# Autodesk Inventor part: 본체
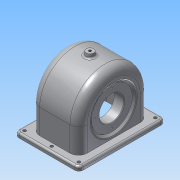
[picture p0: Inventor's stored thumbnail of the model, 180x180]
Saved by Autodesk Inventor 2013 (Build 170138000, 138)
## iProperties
Created: 2015-09
Part Number: 본체
Material: 알루미늄 6061
Document SubType Name: Modeling
Designer: Administrator
Density: 1 g/cm^3
Author: Administrator
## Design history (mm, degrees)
sketch "스케치1"
  geometry: L1 (-57, 0)-(57, 0); L2 (0, 0)-(0, 47); L3 (-57, 0)-(-57, 47); L4 (57, 0)-(57, 47); A1 r 57 centre (0, 47) between (57, 47) and (-57, 47); 1 further point
  constraints: 8 end point, 2 coincident, 2 point on circle, 1 centre point, 1 horizontal, 1 midpoint, 1 parallel, 1 perpendicular
  dimensions: "d0" = 114 distance of L1.start L1.end; "d1" = 47 distance of L2.start L2.end; "d2" = 57 radius of A1
extrude "돌출1" new body sketch "스케치1" stored distance "d3" = 77; taper "d4" = 0 deg
feature "쉘1" dims "d5" = 5
sketch "스케치2"
  geometry: L1 (47, -57)-(0, -57) reference; L2 (0, -57)-(0, 57) reference; L3 (0, 57)-(47, 57) reference; C1 r 31 at (47, 0); A1 r 57 centre (47, 0) between (47, -57) and (47, 57) reference; 1 further point
  constraints: 1 centre point, 1 coincident
  dimensions: "d6" = 62 diameter of C1
extrude "돌출2" join sketch "스케치2" distance "d7" = 10; taper "d8" = 0 deg
sketch "스케치3"
  geometry: C1 r 31 at (0, 0) reference; C2 r 20 at (0, 0); 1 further point
  constraints: 1 centre point, 1 coincident
  dimensions: "d9" = 40 diameter of C2
extrude "돌출3" cut sketch "스케치3" stored distance "d10" = 10; taper "d11" = 0 deg
fillet "모깎기1" dims "d12" = 14
fillet "모깎기2" dims "d13" = 3
chamfer "모따기1" distance "d14" = 1; stored, may be unused: second distance "d15" = 2, angle "d16" = 45 deg
fillet "모깎기3" dims "d17" = 9
sketch "스케치4"
  geometry: C1 r 21 at (0, 0) reference; C2 r 31 at (0, 0) reference; A1 r 24 centre (0, 0) between (0, 24) and (-24, 0); 3 further points
  constraints: 4 point on circle, 1 centre point, 1 coincident
  dimensions: "d18" = 48 diameter of A1
hole "구멍1" sketch "스케치4" at (0, 24), (-24, 0), (0, -24), (24, 0) diameter "d19" = 2.459; stored, may be unused: countersink angle "d23" = 90 deg, drill point angle "d25" = 118 deg; dims "d20" = 6, "d21" = 4, "d22" = 2, "d24" = 8
sketch "스케치5"
  geometry: L1 (0, 43)-(-47, 43) reference; L2 (-47, -43)-(0, -43) reference; L3 (0, 43)-(0, -43) reference; C1 r 28 at (-47, 0); A1 r 43 centre (-47, 0) between (-47, 43) and (-47, -43) reference; 1 further point
  constraints: 1 centre point, 1 coincident
  dimensions: "d26" = 56 diameter of C1
extrude "돌출4" join sketch "스케치5" distance "d27" = 19; taper "d28" = 0 deg
sketch "스케치6"
  geometry: L1 (0, 43)-(-47, 43) reference; L2 (-47, -43)-(0, -43) reference; L3 (0, 43)-(0, -43) reference; C1 r 33 at (-47, 0); A1 r 43 centre (-47, 0) between (-47, 43) and (-47, -43) reference; 1 further point
  constraints: 1 centre point, 1 coincident
  dimensions: "d29" = 66 diameter of C1
extrude "돌출5" cut sketch "스케치6" distance "d30" = 3; taper "d31" = 0 deg
sketch "스케치7"
  geometry: L1 (0, 51.66)-(47, 51.66) reference; L2 (47, 51.66)-(47, -51.66) reference; L3 (47, -51.66)-(0, -51.66) reference; C1 r 33 at (0, 0) reference; C2 r 20 at (0, 0); A1 r 51.66 centre (0, 0) between (0, 51.66) and (0, -51.66) reference; 1 further point
  constraints: 1 centre point, 1 coincident
  dimensions: "d32" = 40 diameter of C2
extrude "돌출6" cut sketch "스케치7" stored distance "d33" = 3; taper "d34" = 0 deg
feature "면 기울기1" dims angle "d35" = 40 deg
node "작업 평면1"
sketch "스케치8"
  geometry: L1 (44, -19)-(58, -7.253) reference; L2 (58, -7.253)-(58, 0) reference; L3 (58, 0)-(63, 0) reference; L4 (63, 0)-(63, -14) reference; L5 (63, -14)-(60, -14) reference; L6 (60, -14)-(60, -27) reference; L7 (60, -27)-(44, -27) reference; L8 (44, -27)-(44, -19) reference; L9 (-14, -13)-(-14, 0) reference; L10 (-14, 0)-(-9, 0) reference; L11 (-9, 0)-(-9, -27) reference; L12 (-9, -27)-(-23, -27) reference; L13 (-23, -27)-(-24, -26) reference; L14 (-24, -26)-(-24, -24.229) reference; L15 (-24, -24.229)-(-16, -24.229) reference; L16 (-16, -24.229)-(-15.261, -23) reference; L17 (-15.261, -23)-(-16, -21.77) reference; L18 (-16, -21.77)-(-24, -21.77) reference; L19 (-24, -21.77)-(-24, -16) reference; L20 (-24, -16)-(-17, -16) reference; L21 (49, -104)-(0, -104) reference; L22 (-14, -90)-(-14, -81) reference; L23 (-17, -78)-(-24, -78) reference; L24 (-24, -78)-(-24, -72.23) reference; L25 (-24, -72.23)-(-16, -72.23) reference; L26 (-16, -72.23)-(-15.261, -71) reference; L27 (-15.261, -71)-(-16, -69.77) reference; L28 (-16, -69.77)-(-24, -69.77) reference; L29 (-24, -69.77)-(-24, -68) reference; L30 (-24, -68)-(-23, -67) reference; L31 (-23, -67)-(-9, -67) reference; L32 (-9, -67)-(-9, -90) reference; L33 (0, -99)-(49, -99) reference; L34 (58, -90)-(58, -86.747) reference; L35 (58, -86.747)-(44, -75) reference; L36 (44, -75)-(44, -67) reference; L37 (44, -67)-(60, -67) reference; L38 (60, -67)-(60, -80) reference; L39 (60, -80)-(63, -80) reference; L40 (63, -80)-(63, -90) reference; L41 (58, -86.747)-(44, -75); L42 (63, -84.416)-(58.79, -80.883); L43 (63, -84.416)-(63, -80); L44 (63, -80)-(59.111, -80); L45 (60, -67)-(60, -27); L46 (60, -47)-(88.26, -47); A1 r 3 centre (-17, -13) between (-17, -16) and (-14, -13) reference; A2 r 14 centre (49, -90) between (49, -104) and (63, -90) reference; A3 r 14 centre (0, -90) between (-14, -90) and (0, -104) reference; A4 r 3 centre (-17, -81) between (-14, -81) and (-17, -78) reference; A5 r 9 centre (0, -90) between (-9, -90) and (0, -99) reference; A6 r 9 centre (49, -90) between (49, -99) and (58, -90) reference; A7 r 0.5 centre (59.111, -80.5) between (59.111, -80) and (58.79, -80.883); 1 further point
  constraints: 12 end point, 3 perpendicular, 2 collinear, 2 point on circle, 2 tangent, 1 centre point, 1 midpoint, 1 parallel, 1 point on line
  dimensions: "d36" = 5 distance between parallel lines of L35 L42; "d37" = 0.5 radius of A7
revolve "회전1" sketch "스케치8" stored, may be unused: angle "d38" = 90 deg
chamfer "모따기2" distance "d39" = 1; stored, may be unused: second distance "d40" = 2, angle "d41" = 45 deg
sketch "스케치9"
  geometry: L1 (0, 51.66)-(47, 51.66) reference; L2 (47, 51.66)-(47, -51.66) reference; L3 (47, -51.66)-(0, -51.66) reference; C1 r 21 at (0, 0) reference; C2 r 34.899 at (0, 0) reference; C3 r 33 at (0, 0) reference; A1 r 51.66 centre (0, 0) between (0, 51.66) and (0, -51.66) reference; A2 r 28 centre (0, 0) between (-28, 0) and (0, -28); 3 further points
  constraints: 4 point on circle, 1 centre point, 1 coincident
  dimensions: "d42" = 56 diameter of A2
hole "구멍2" sketch "스케치9" at (-28, 0), (0, -28), (28, 0), (0, 28) diameter "d43" = 2.459; stored, may be unused: countersink angle "d47" = 82 deg, drill point angle "d49" = 118 deg; dims "d44" = 7, "d45" = 3.023, "d46" = 2, "d48" = 9
sketch "스케치10"
  geometry: L1 (-33.5, 43)-(-33.5, -43) reference; L2 (-24.5, -52)-(24.5, -52) reference; L3 (33.5, -43)-(33.5, 43) reference; L4 (24.5, 52)-(-24.5, 52) reference; L5 (-38.5, -43)-(-38.5, 43) reference; L6 (-24.5, 57)-(24.5, 57) reference; L7 (38.5, 43)-(38.5, -43) reference; L8 (24.5, -57)-(-24.5, -57) reference; L9 (-45, 70)-(45, 70); L10 (52, 63)-(52, -63); L11 (45, -70)-(-45, -70); L12 (-52, -63)-(-52, 63); L13 (0, 70)-(0, 62); L14 (-38.5, 0)-(38.5, 0); C1 r 2.5 at (-44, 62); C2 r 2.5 at (0, 62); C3 r 2.5 at (44, 62); C4 r 2.5 at (-44, -62); C5 r 2.5 at (0, -62); C6 r 2.5 at (44, -62); A1 r 9 centre (-24.5, 43) between (-24.5, 52) and (-33.5, 43) reference; A2 r 9 centre (-24.5, -43) between (-33.5, -43) and (-24.5, -52) reference; A3 r 9 centre (24.5, -43) between (24.5, -52) and (33.5, -43) reference; A4 r 9 centre (24.5, 43) between (33.5, 43) and (24.5, 52) reference; A5 r 14 centre (-24.5, 43) between (-24.5, 57) and (-38.5, 43) reference; A6 r 14 centre (24.5, 43) between (38.5, 43) and (24.5, 57) reference; A7 r 14 centre (24.5, -43) between (24.5, -57) and (38.5, -43) reference; A8 r 14 centre (-24.5, -43) between (-38.5, -43) and (-24.5, -57) reference; A9 r 7 centre (-45, 63) between (-45, 70) and (-52, 63); A10 r 7 centre (45, 63) between (52, 63) and (45, 70); A11 r 7 centre (45, -63) between (45, -70) and (52, -63); A12 r 7 centre (-45, -63) between (-52, -63) and (-45, -70); 5 further points
  constraints: 12 end point, 10 centre point, 8 point on circle, 8 tangent, 6 point on line, 4 midpoint, 3 equal radius, 3 symmetric about line, 2 parallel, 1 coincident, 1 horizontal, 1 horizontal alignment, 1 perpendicular, 1 vertical alignment, 3 other
  dimensions: "d50" = 104 distance of point (52, -70) point (-52, -70); "d51" = 140 distance of point (52, 70) point (52, -70); "d52" = 7 radius of A9; "d57" = 5 diameter of C1; "d58" = 5 diameter of C2; "d59" = 5 diameter of C3
extrude "돌출7" join sketch "스케치10" distance "d60" = 7; taper "d61" = 0 deg
fillet "모깎기4" dims "d62" = 3
node "작업 평면3"
  node "작업 평면2"
sketch "스케치11"
  geometry: C1 r 6 at (0, 0); 1 further point
  constraints: 1 centre point, 1 coincident
  dimensions: "d64" = 12 diameter of C1
extrude "돌출8" join sketch "스케치11" stored distance "d65" = 7; taper "d66" = 0 deg
feature "면 기울기2" dims angle "d67" = 10 deg
fillet "모깎기5" dims "d68" = 3
sketch "스케치12"
  geometry: C1 r 6 at (0, 0) reference; 1 further point
hole "구멍3" sketch "스케치12" at (0, 0) diameter "d69" = 4.134; stored, may be unused: countersink angle "d73" = 82 deg, drill point angle "d75" = 118 deg; dims "d70" = 10, "d71" = 3.023, "d72" = 2, "d74" = 20
sketch "스케치13"
  geometry: L1 (73.5, 40)-(49, 40) reference; L2 (49, 40)-(0, 40) reference; L3 (0, 40)-(-24.5, 40) reference; L4 (-27.5, 43)-(-27.5, 47) reference; L5 (-27.5, 47)-(76.5, 47) reference; L6 (76.5, 47)-(76.5, 43) reference; L7 (49, 40)-(49, 0) reference; L8 (0, 0)-(49, 0) reference; L9 (0, 0)-(0, 40) reference; L10 (63, 0)-(63, 40) reference; A1 r 3 centre (73.5, 43) between (73.5, 40) and (76.5, 43) reference; A2 r 3 centre (-24.5, 43) between (-27.5, 43) and (-24.5, 40) reference; 2 further points
  constraints: 1 other
  dimensions: "d76" = 30 vertical distance of point (24.5, 17) L5.end; "d77" = 38.5 horizontal distance of point (24.5, 17) L10.end
feature "엠보싱1" sketch "스케치13" dims "d78" = 0.5, "d79" = 0
node "솔리드1"
node "절단 모서리 투영1"
node "절단 모서리 투영2"
node "절단 모서리 투영3"
node "절단 모서리 투영4"
node "절단 모서리 투영5"
node "절단 모서리 투영6"
node "절단 모서리 투영7"
node "절단 모서리 투영8"
node "절단 모서리 투영9"
node "절단 모서리 투영10"
node "절단 모서리 투영11"
other parameters: "d63" = 6
